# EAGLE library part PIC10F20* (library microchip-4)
uPC nW 0,25/0,5k Program Flash memory
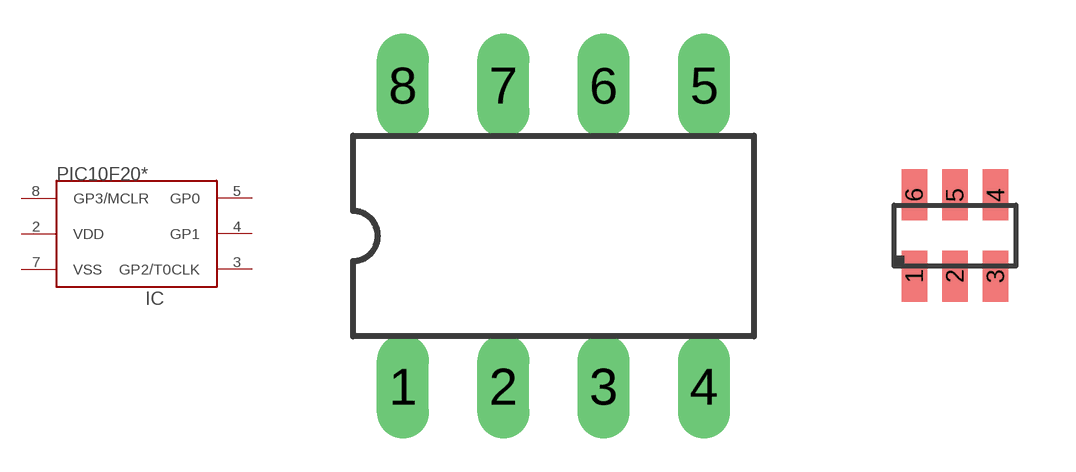
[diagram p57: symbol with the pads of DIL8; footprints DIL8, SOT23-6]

Designator prefix IC

## PIC10F200P, PIC10F202P  [DIL8]
2  VDD  pwr
3  GP2/T0CLK
4  GP1
5  GP0
7  VSS  pwr
8  GP3/MCLR  in

## PIC10F200OT, PIC10F202OT  [SOT23-6]
1  GP0
2  VSS  pwr
3  GP1
4  GP2/T0CLK
5  VDD  pwr
6  GP3/MCLR  in

## Footprint DIL8 (pad centres in mm)
Dual In Line package type P
drill 0.813 long: 1 -3.81,-3.81; 2 -1.27,-3.81; 3 1.27,-3.81; 4 3.81,-3.81; 5 3.81,3.81; 6 1.27,3.81; 7 -1.27,3.81; 8 -3.81,3.81

## Footprint SOT23-6 (pad centres in mm)
SMD 3x1,75mm /6pin
smd 0.635 x 1.27: 1 -1.016,-1.016; 2 0,-1.016; 3 1.016,-1.016; 4 1.016,1.016; 5 0,1.016; 6 -1.016,1.016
